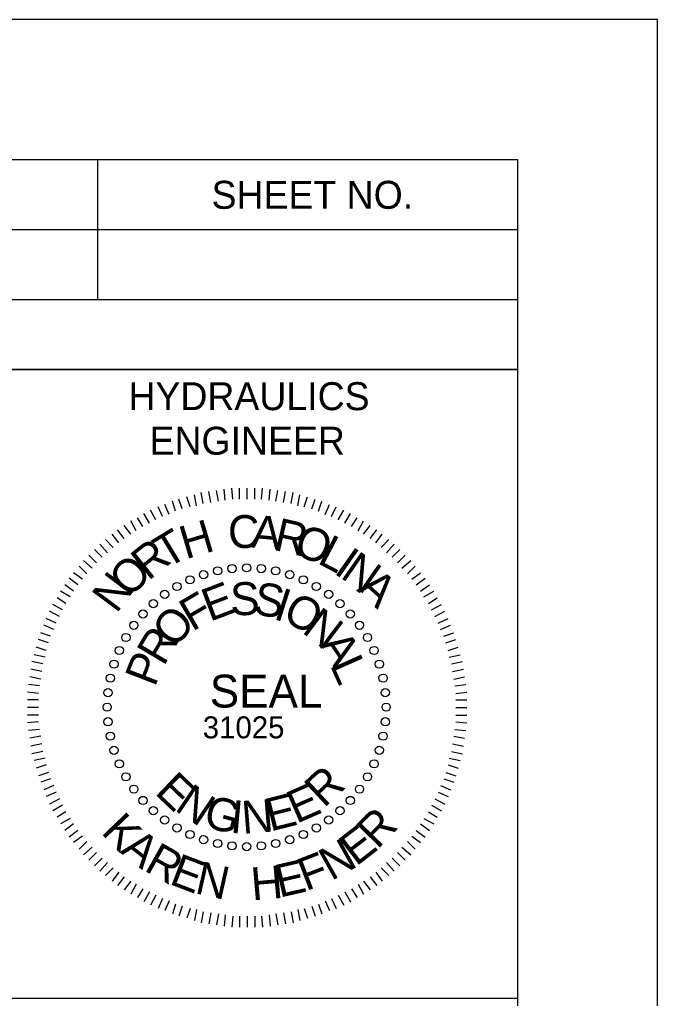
# Model space of a CAD drawing. Extents: x 573078 to 573117.1, y -55221.3 to -55199.3.
# Drawn here: x 573109.734 to 573112.014, y -55202.8 to -55199.298 of the extents above; entities that cross this region are included whole.
import ezdxf

# ---------------------------------------------------------------- set-up
doc = ezdxf.new("R2010")
doc.units = 0
for name, color, linetype in [('Old_Level_5', 7, 'Continuous'), ('Scratch_Level_1', 7, 'Continuous'), ('Sheet Clip Boundary CELL', 7, 'Continuous'), ('Sheet Plan CELL', 7, 'Continuous'), ('Sheet Plot Border Inside CELL', 7, 'Continuous')]:
    doc.layers.add(name, color=color, linetype=linetype)

msp = doc.modelspace()

# ---------------------------------------------------------------- linework, layer by layer
at = {"layer": 'Old_Level_5'}
for p, q in [((573110.4966, -55201.0136), (573110.4929, -55200.9742)), ((573110.5204, -55201.0136), (573110.5204, -55200.9742)), ((573110.5479, -55201.0136), (573110.5479, -55200.9742)), ((573110.5479, -55201.0136), (573110.5479, -55200.9742)), ((573110.5479, -55201.0136), (573110.5479, -55200.9742)), ((573110.5479, -55201.0136), (573110.5479, -55200.9742)), ((573110.5479, -55201.0136), (573110.5479, -55200.9742)), ((573110.5479, -55201.0136), (573110.5479, -55200.9742)), ((573110.5479, -55201.0136), (573110.5479, -55200.9742)), ((573110.5479, -55201.0136), (573110.5479, -55200.9742)), ((573110.5479, -55201.0136), (573110.5479, -55200.9742)), ((573110.5479, -55201.0136), (573110.5479, -55200.9742)), ((573110.5479, -55201.0136), (573110.5479, -55200.9742)), ((573110.5479, -55201.0136), (573110.5479, -55200.9742)), ((573110.5479, -55201.0136), (573110.5479, -55200.9742)), ((573110.5479, -55201.0136), (573110.5479, -55200.9742)), ((573110.5479, -55201.0136), (573110.5479, -55200.9742)), ((573110.5479, -55201.0136), (573110.5479, -55200.9742)), ((573110.5479, -55201.0136), (573110.5479, -55200.9742)), ((573110.5479, -55201.0136), (573110.5479, -55200.9742)), ((573110.5479, -55201.0136), (573110.5479, -55200.9742)), ((573110.5479, -55201.0136), (573110.5479, -55200.9742)), ((573110.5479, -55201.0136), (573110.5479, -55200.9742)), ((573110.5479, -55201.0136), (573110.5479, -55200.9742)), ((573110.5479, -55201.0136), (573110.5479, -55200.9742)), ((573110.5479, -55201.0136), (573110.5479, -55200.9742)), ((573110.5479, -55201.0136), (573110.5479, -55200.9742)), ((573110.5479, -55201.0136), (573110.5479, -55200.9742)), ((573110.5479, -55201.0136), (573110.5479, -55200.9742)), ((573110.5479, -55201.0136), (573110.5479, -55200.9742)), ((573110.5479, -55201.0136), (573110.5479, -55200.9742)), ((573110.5479, -55201.0136), (573110.5479, -55200.9742)), ((573110.5754, -55201.0136), (573110.5754, -55200.9742)), ((573110.5985, -55201.0136), (573110.6029, -55200.9742)), ((573110.3435, -55201.0411), (573110.3316, -55201.0055)), ((573110.3672, -55201.0373), (573110.3591, -55200.998)), ((573110.3904, -55201.0292), (573110.3829, -55200.9898)), ((573110.4179, -55201.0255), (573110.4104, -55200.9861)), ((573110.4454, -55201.0211), (573110.4379, -55200.9823)), ((573110.4691, -55201.0173), (573110.4654, -55200.978)), ((573110.626, -55201.0173), (573110.6304, -55200.978)), ((573110.6497, -55201.0211), (573110.6579, -55200.9823)), ((573110.6772, -55201.0255), (573110.6847, -55200.9861)), ((573110.7047, -55201.0292), (573110.7122, -55200.9898)), ((573110.7285, -55201.0373), (573110.736, -55200.998)), ((573110.7516, -55201.0411), (573110.7635, -55201.0055)), ((573110.2454, -55201.0761), (573110.2297, -55201.0411)), ((573110.2691, -55201.0686), (573110.2535, -55201.033)), ((573110.2922, -55201.0567), (573110.281, -55201.0211)), ((573110.316, -55201.0486), (573110.3041, -55201.0136)), ((573110.7791, -55201.0486), (573110.791, -55201.0136)), ((573110.8029, -55201.0567), (573110.8147, -55201.0211)), ((573110.8266, -55201.0686), (573110.8422, -55201.033)), ((573110.8497, -55201.0761), (573110.8654, -55201.0411)), ((573110.1747, -55201.1117), (573110.1554, -55201.0805)), ((573110.1985, -55201.0998), (573110.1785, -55201.0648)), ((573110.2216, -55201.088), (573110.2022, -55201.053)), ((573110.8735, -55201.088), (573110.8929, -55201.053)), ((573110.8972, -55201.0998), (573110.9166, -55201.0648)), ((573110.9204, -55201.1117), (573110.9404, -55201.0805)), ((573110.1316, -55201.1392), (573110.1079, -55201.108)), ((573110.151, -55201.1273), (573110.1316, -55201.0917)), ((573110.9441, -55201.1273), (573110.9635, -55201.0917)), ((573110.9635, -55201.1392), (573110.9872, -55201.108)), ((573110.0885, -55201.1705), (573110.0647, -55201.1392)), ((573110.1079, -55201.1548), (573110.0847, -55201.1236)), ((573110.9872, -55201.1548), (573111.011, -55201.1236)), ((573111.0072, -55201.1705), (573111.0304, -55201.1392)), ((573110.0491, -55201.2061), (573110.0216, -55201.1742)), ((573110.0685, -55201.1861), (573110.041, -55201.1586)), ((573111.0266, -55201.1861), (573111.0541, -55201.1586)), ((573111.046, -55201.2061), (573111.0735, -55201.1742)), ((573110.0097, -55201.2411), (573109.9822, -55201.2136)), ((573110.0297, -55201.2217), (573110.0022, -55201.1942)), ((573111.066, -55201.2217), (573111.0935, -55201.1942)), ((573111.0854, -55201.2411), (573111.1129, -55201.2136)), ((573109.9747, -55201.2805), (573109.9472, -55201.253)), ((573109.9941, -55201.2611), (573109.9629, -55201.2336)), ((573111.101, -55201.2611), (573111.1329, -55201.2336)), ((573111.121, -55201.2805), (573111.1485, -55201.253)), ((573109.9591, -55201.2998), (573109.9272, -55201.2767)), ((573111.1366, -55201.2998), (573111.1679, -55201.2767)), ((573109.9272, -55201.343), (573109.896, -55201.3198)), ((573109.9429, -55201.3198), (573109.9116, -55201.2961)), ((573111.1522, -55201.3198), (573111.1835, -55201.2961)), ((573111.1679, -55201.343), (573111.1991, -55201.3198)), ((573109.9154, -55201.363), (573109.8804, -55201.343)), ((573111.1797, -55201.363), (573111.2147, -55201.343)), ((573109.8879, -55201.4098), (573109.8529, -55201.3905)), ((573109.8997, -55201.3867), (573109.8685, -55201.3667)), ((573111.1954, -55201.3867), (573111.2266, -55201.3667)), ((573111.2072, -55201.4098), (573111.2422, -55201.3905)), ((573109.8766, -55201.4336), (573109.841, -55201.4142)), ((573111.2191, -55201.4336), (573111.2541, -55201.4142)), ((573109.8566, -55201.4805), (573109.8216, -55201.4648)), ((573109.8647, -55201.4573), (573109.8291, -55201.4411)), ((573111.231, -55201.4573), (573111.266, -55201.4411)), ((573111.2385, -55201.4805), (573111.2741, -55201.4648)), ((573109.8447, -55201.5042), (573109.8097, -55201.4923)), ((573111.2504, -55201.5042), (573111.286, -55201.4923)), ((573109.8372, -55201.528), (573109.8016, -55201.5161)), ((573111.2585, -55201.528), (573111.2935, -55201.5161)), ((573109.8254, -55201.5786), (573109.786, -55201.5711)), ((573109.8291, -55201.5555), (573109.7941, -55201.5436)), ((573111.266, -55201.5555), (573111.3016, -55201.5436)), ((573111.2697, -55201.5786), (573111.3091, -55201.5711)), ((573109.8172, -55201.6023), (573109.7785, -55201.5942)), ((573111.2779, -55201.6023), (573111.3172, -55201.5942)), ((573109.8135, -55201.6298), (573109.7741, -55201.6217)), ((573111.2816, -55201.6298), (573111.321, -55201.6217)), ((573109.806, -55201.6811), (573109.7666, -55201.6767)), ((573109.8097, -55201.6573), (573109.7704, -55201.6492)), ((573111.286, -55201.6573), (573111.3247, -55201.6492)), ((573111.2897, -55201.6811), (573111.3291, -55201.6767)), ((573109.8016, -55201.7086), (573109.7629, -55201.7042)), ((573111.2935, -55201.7086), (573111.3329, -55201.7042)), ((573109.8016, -55201.7317), (573109.7629, -55201.7317)), ((573111.2935, -55201.7317), (573111.3329, -55201.7317)), ((573109.8016, -55201.7592), (573109.7629, -55201.7592)), ((573111.2935, -55201.7592), (573111.3329, -55201.7592)), ((573109.8016, -55201.7867), (573109.7629, -55201.7867)), ((573109.8016, -55201.8105), (573109.7629, -55201.8142)), ((573111.2935, -55201.7867), (573111.3329, -55201.7867)), ((573111.2935, -55201.8105), (573111.3329, -55201.8142)), ((573109.806, -55201.838), (573109.7666, -55201.8417)), ((573111.2897, -55201.838), (573111.3291, -55201.8417)), ((573109.8097, -55201.8611), (573109.7704, -55201.8692)), ((573111.286, -55201.8611), (573111.3247, -55201.8692)), ((573109.8135, -55201.8886), (573109.7741, -55201.8967)), ((573109.8172, -55201.9161), (573109.7785, -55201.9242)), ((573111.2779, -55201.9161), (573111.3172, -55201.9242)), ((573111.2816, -55201.8886), (573111.321, -55201.8967)), ((573109.8254, -55201.9398), (573109.786, -55201.948)), ((573111.2697, -55201.9398), (573111.3091, -55201.948)), ((573109.8291, -55201.9636), (573109.7941, -55201.9755)), ((573109.8372, -55201.9911), (573109.8016, -55202.003)), ((573111.2585, -55201.9911), (573111.2935, -55202.003)), ((573111.266, -55201.9636), (573111.3016, -55201.9755)), ((573109.8447, -55202.0142), (573109.8097, -55202.0261)), ((573111.2504, -55202.0142), (573111.286, -55202.0261)), ((573109.8566, -55202.038), (573109.8216, -55202.0536)), ((573109.8647, -55202.0617), (573109.8291, -55202.0773)), ((573111.231, -55202.0617), (573111.266, -55202.0773)), ((573111.2385, -55202.038), (573111.2741, -55202.0536)), ((573109.8766, -55202.0855), (573109.841, -55202.1048)), ((573111.2191, -55202.0855), (573111.2541, -55202.1048)), ((573109.8879, -55202.1086), (573109.8529, -55202.1286)), ((573109.8997, -55202.1323), (573109.8685, -55202.1517)), ((573111.1954, -55202.1323), (573111.2266, -55202.1517)), ((573111.2072, -55202.1086), (573111.2422, -55202.1286)), ((573109.9154, -55202.1561), (573109.8804, -55202.1755)), ((573111.1797, -55202.1561), (573111.2147, -55202.1755)), ((573109.9272, -55202.1755), (573109.896, -55202.1992)), ((573109.9429, -55202.1992), (573109.9116, -55202.2223)), ((573111.1522, -55202.1992), (573111.1835, -55202.2223)), ((573111.1679, -55202.1755), (573111.1991, -55202.1992)), ((573109.9591, -55202.2186), (573109.9272, -55202.2423)), ((573111.1366, -55202.2186), (573111.1679, -55202.2423)), ((573109.9747, -55202.2386), (573109.9472, -55202.2655)), ((573109.9941, -55202.258), (573109.9629, -55202.2855)), ((573111.101, -55202.258), (573111.1329, -55202.2855)), ((573111.121, -55202.2386), (573111.1485, -55202.2655)), ((573110.0097, -55202.2773), (573109.9822, -55202.3048)), ((573110.0297, -55202.2973), (573110.0022, -55202.3248)), ((573111.066, -55202.2973), (573111.0935, -55202.3248)), ((573111.0854, -55202.2773), (573111.1129, -55202.3048)), ((573110.0491, -55202.313), (573110.0216, -55202.3442)), ((573110.0685, -55202.3323), (573110.041, -55202.3598)), ((573111.0266, -55202.3323), (573111.0541, -55202.3598)), ((573111.046, -55202.313), (573111.0735, -55202.3442)), ((573110.0885, -55202.348), (573110.0647, -55202.3798)), ((573110.1079, -55202.3642), (573110.0847, -55202.3955)), ((573110.9872, -55202.3642), (573111.011, -55202.3955)), ((573111.0072, -55202.348), (573111.0304, -55202.3798)), ((573110.1316, -55202.3798), (573110.1079, -55202.4111)), ((573110.151, -55202.3911), (573110.1316, -55202.4267)), ((573110.1747, -55202.4073), (573110.1554, -55202.4386)), ((573110.9204, -55202.4073), (573110.9404, -55202.4386)), ((573110.9441, -55202.3911), (573110.9635, -55202.4267)), ((573110.9635, -55202.3798), (573110.9872, -55202.4111)), ((573110.1985, -55202.4186), (573110.1785, -55202.4542)), ((573110.2216, -55202.4305), (573110.2022, -55202.4661)), ((573110.2454, -55202.4423), (573110.2297, -55202.478)), ((573110.8497, -55202.4423), (573110.8654, -55202.478)), ((573110.8735, -55202.4305), (573110.8929, -55202.4661)), ((573110.8972, -55202.4186), (573110.9166, -55202.4542)), ((573110.2691, -55202.4505), (573110.2535, -55202.4855)), ((573110.2922, -55202.4623), (573110.281, -55202.4973)), ((573110.316, -55202.4698), (573110.3041, -55202.5055)), ((573110.3435, -55202.478), (573110.3316, -55202.513)), ((573110.3672, -55202.4817), (573110.3591, -55202.5211)), ((573110.7285, -55202.4817), (573110.736, -55202.5211)), ((573110.7516, -55202.478), (573110.7635, -55202.513)), ((573110.7791, -55202.4698), (573110.791, -55202.5055)), ((573110.8029, -55202.4623), (573110.8147, -55202.4973)), ((573110.8266, -55202.4505), (573110.8422, -55202.4855)), ((573110.3904, -55202.4898), (573110.3829, -55202.5286)), ((573110.4179, -55202.4936), (573110.4104, -55202.533)), ((573110.4454, -55202.4973), (573110.4379, -55202.5367)), ((573110.4691, -55202.5011), (573110.4654, -55202.5405)), ((573110.4966, -55202.5055), (573110.4929, -55202.5442)), ((573110.5204, -55202.5055), (573110.5204, -55202.5442)), ((573110.5479, -55202.5055), (573110.5479, -55202.5442)), ((573110.5754, -55202.5055), (573110.5754, -55202.5442)), ((573110.5985, -55202.5055), (573110.6029, -55202.5442)), ((573110.626, -55202.5011), (573110.6304, -55202.5405)), ((573110.6497, -55202.4973), (573110.6579, -55202.5367)), ((573110.6772, -55202.4936), (573110.6847, -55202.533)), ((573110.7047, -55202.4898), (573110.7122, -55202.5286))]:
    msp.add_line(p, q, dxfattribs=at)
for centre in [(573110.4424, -55201.2702), (573110.4424, -55201.2702), (573110.4939, -55201.262), (573110.4939, -55201.262), (573110.546, -55201.2593), (573110.546, -55201.2593), (573110.5981, -55201.262), (573110.6497, -55201.2702), (573110.3432, -55201.3024), (573110.3432, -55201.3024), (573110.392, -55201.2837), (573110.392, -55201.2837), (573110.7001, -55201.2837), (573110.7488, -55201.3024), (573110.2968, -55201.3261), (573110.2968, -55201.3261), (573110.7953, -55201.3261), (573110.253, -55201.3545), (573110.253, -55201.3545), (573110.8391, -55201.3545), (573110.2124, -55201.3874), (573110.2124, -55201.3874), (573110.8796, -55201.3874), (573110.1755, -55201.4243), (573110.1755, -55201.4243), (573110.9165, -55201.4243), (573110.1427, -55201.4648), (573110.1427, -55201.4648), (573110.9494, -55201.4648), (573110.1143, -55201.5086), (573110.1143, -55201.5086), (573110.9778, -55201.5086), (573110.0906, -55201.5551), (573110.0906, -55201.5551), (573111.0015, -55201.5551), (573110.0719, -55201.6038), (573110.0719, -55201.6038), (573111.0202, -55201.6038), (573110.0584, -55201.6542), (573110.0584, -55201.6542), (573111.0337, -55201.6542), (573110.0502, -55201.7057), (573110.0502, -55201.7057), (573111.0418, -55201.7057), (573110.0475, -55201.7578), (573110.0475, -55201.7578), (573111.0446, -55201.7578), (573110.0502, -55201.81), (573110.0502, -55201.81), (573111.0418, -55201.81), (573110.0584, -55201.8615), (573110.0584, -55201.8615), (573111.0337, -55201.8615), (573110.0719, -55201.9119), (573110.0719, -55201.9119), (573111.0202, -55201.9119), (573110.0906, -55201.9606), (573110.0906, -55201.9606), (573111.0015, -55201.9606), (573110.1143, -55202.0071), (573110.1143, -55202.0071), (573110.9778, -55202.0071), (573110.1427, -55202.0509), (573110.1427, -55202.0509), (573110.9494, -55202.0509), (573110.1755, -55202.0914), (573110.1755, -55202.0914), (573110.9165, -55202.0914), (573110.2124, -55202.1283), (573110.2124, -55202.1283), (573110.8796, -55202.1283), (573110.253, -55202.1612), (573110.253, -55202.1612), (573110.8391, -55202.1612), (573110.2968, -55202.1896), (573110.2968, -55202.1896), (573110.3432, -55202.2133), (573110.3432, -55202.2133), (573110.7488, -55202.2133), (573110.7953, -55202.1896), (573110.392, -55202.232), (573110.392, -55202.232), (573110.4424, -55202.2455), (573110.4424, -55202.2455), (573110.6497, -55202.2455), (573110.7001, -55202.232), (573110.4939, -55202.2537), (573110.4939, -55202.2537), (573110.546, -55202.2564), (573110.5981, -55202.2537)]:
    msp.add_circle(centre, 0.0147, dxfattribs=at)
at = {"layer": 'Scratch_Level_1'}
msp.add_line((573110.547, -55201.7592), (573110.547, -55201.7592), dxfattribs=at)
at = {"layer": 'Sheet Clip Boundary CELL'}
msp.add_line((573111.8452, -55201.263), (573111.8452, -55201.263), dxfattribs=at)
at = {"layer": 'Sheet Plan CELL'}
for p, q in [((573110.0144, -55200.2999), (573110.0144, -55199.7984)), ((573107.5132, -55200.0494), (573111.5142, -55200.0497)), ((573107.5132, -55200.3002), (573111.5142, -55200.2997))]:
    msp.add_line(p, q, dxfattribs=at)
for points in [[(573081.5142, -55199.7984), (573111.5142, -55199.7984), (573111.5142, -55220.7984), (573081.5142, -55220.7984)], [(573107.5132, -55199.7984), (573111.5142, -55199.7984), (573111.5142, -55200.5499), (573107.5132, -55200.5499)], [(573109.5142, -55200.5499), (573111.5142, -55200.5499), (573111.5142, -55202.7999), (573109.5142, -55202.7999)]]:
    msp.add_lwpolyline(points, close=True, dxfattribs=at)
at = {"layer": 'Sheet Plot Border Inside CELL'}
msp.add_lwpolyline([(573112.0142, -55199.2984), (573078.0142, -55199.2984), (573078.0142, -55221.2984), (573112.0142, -55221.2984)], close=True, dxfattribs=at)

# ---------------------------------------------------------------- texts
at = {"layer": 'Old_Level_5'}
for s, height, rotation, p in [('C', 0.1178, 1.8409, (573110.481, -55201.1905)), ('A', 0.1178, 354.4936, (573110.5591, -55201.1861)), ('T', 0.1178, 31.23, (573110.261, -55201.2648)), ('H', 0.1178, 16.5355, (573110.3279, -55201.2292)), ('R', 0.1173, 347.1464, (573110.6379, -55201.1942)), ('O', 0.1178, 339.7991, (573110.7085, -55201.2098)), ('L', 0.1173, 332.4518, (573110.7947, -55201.2411)), ('R', 0.1178, 38.5773, (573110.1941, -55201.308)), ('I', 0.1178, 325.1046, (573110.8541, -55201.2767)), ('N', 0.1178, 325.1046, (573110.8772, -55201.2923)), ('O', 0.1178, 45.9246, (573110.1279, -55201.3705)), ('N', 0.1178, 53.2718, (573110.0804, -55201.4255)), ('A', 0.1178, 317.7573, (573110.9366, -55201.3392)), ('E', 0.1178, 20.7502, (573110.4141, -55201.453)), ('S', 0.1178, 1.4893, (573110.4885, -55201.4298)), ('S', 0.1178, 351.8588, (573110.5672, -55201.4255)), ('F', 0.1173, 30.3806, (573110.3516, -55201.4886)), ('I', 0.1178, 342.2284, (573110.6379, -55201.4411)), ('O', 0.1178, 332.5979, (573110.6691, -55201.4455)), ('O', 0.1178, 49.6415, (573110.2885, -55201.5511)), ('N', 0.1178, 322.9675, (573110.7397, -55201.4886)), ('R', 0.1178, 59.272, (573110.2491, -55201.6142)), ('A', 0.1178, 303.7066, (573110.8029, -55201.5355)), ('P', 0.1178, 68.9024, (573110.2179, -55201.6886)), ('L', 0.1178, 294.0761, (573110.8422, -55201.6061)), ('E', 0.1178, 316.3156, (573110.2141, -55202.0655)), ('R', 0.1178, 42.9896, (573110.8222, -55202.1205)), ('N', 0.1178, 325.946, (573110.2847, -55202.1242)), ('E', 0.1173, 23.7287, (573110.7241, -55202.1755)), ('G', 0.1178, 345.2069, (573110.3866, -55202.1836)), ('I', 0.1178, 354.8374, (573110.4847, -55202.2067)), ('N', 0.1173, 4.4678, (573110.5322, -55202.2111)), ('E', 0.1178, 14.0983, (573110.6304, -55202.203)), ('R', 0.1175, 45.7969, (573111.0136, -55202.2685)), ('K', 0.1175, 313.7767, (573110.0225, -55202.2067)), ('E', 0.1175, 37.6963, (573110.9371, -55202.329)), ('A', 0.1175, 321.8774, (573110.0908, -55202.2762)), ('N', 0.1175, 29.1693, (573110.8484, -55202.3804)), ('R', 0.1175, 330.6886, (573110.1754, -55202.3401)), ('E', 0.1175, 339.2155, (573110.2656, -55202.389)), ('E', 0.1175, 12.9681, (573110.6631, -55202.4396)), ('F', 0.1175, 21.0687, (573110.7578, -55202.4166)), ('N', 0.1175, 347.3161, (573110.3572, -55202.4224)), ('H', 0.1175, 4.8675, (573110.5661, -55202.4491))]:
    msp.add_text(s, height=height, rotation=rotation, dxfattribs=at).set_placement(p)
for s, height, p in [('SEAL', 0.11777, (573110.4141, -55201.7592)), ('31025', 0.0785, (573110.3891, -55201.8692))]:
    msp.add_text(s, height=height, dxfattribs=at).set_placement(p)
at = {"layer": 'Sheet Plan CELL'}
for s, p in [('SHEET NO.', (573110.4204, -55199.9752)), ('HYDRAULICS', (573110.1234, -55200.6954)), ('ENGINEER', (573110.1987, -55200.8547))]:
    msp.add_text(s, height=0.1, rotation=0, dxfattribs=at).set_placement(p)

doc.saveas('drawing.dxf')
